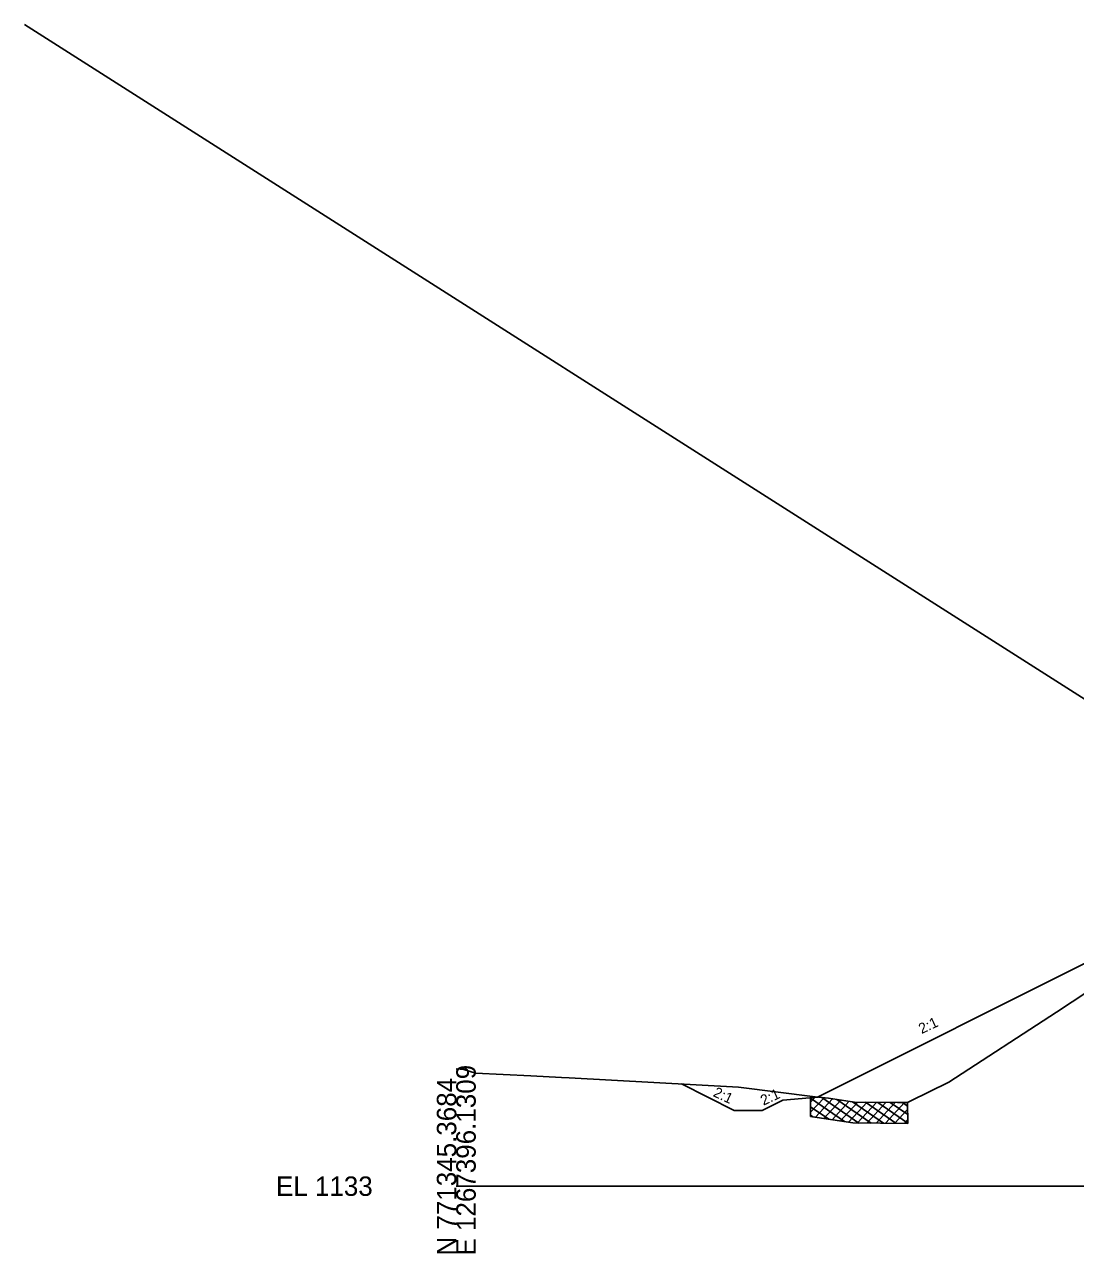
# Model space of a CAD drawing. Extents: x -3833 to 1267678, y -522 to 773248.
# Drawn here: x -62.2 to 89.3, y 7990.3 to 8167.4 of the extents above; entities that cross this region are included whole.
import ezdxf

# ---------------------------------------------------------------- set-up
doc = ezdxf.new("R2010")
doc.units = 0
for name, color, linetype in [('Exist Cross Section Cell', 7, 'Continuous'), ('Exist XS Ground Line', 7, 'Continuous'), ('Prop CMT DNC', 7, 'Continuous'), ('Prop XS Finish Grade', 7, 'Continuous'), ('Prop XS Label Text', 7, 'Continuous'), ('Prop XS Undercut Exc', 7, 'Continuous'), ('Scratch_Level_1', 7, 'Continuous')]:
    doc.layers.add(name, color=color, linetype=linetype)

msp = doc.modelspace()

# ---------------------------------------------------------------- linework, layer by layer
at = {"layer": 'Exist Cross Section Cell'}
msp.add_line((0, 8000), (150, 8000), dxfattribs=at)
at = {"layer": 'Exist XS Ground Line'}
for p, q in [((86.52, 8025.06), (97, 8032.03)), ((71.03, 8015.01), (86.52, 8025.06)), ((0, 8016.91), (1.11, 8016.8)), ((1.11, 8016.8), (2.77, 8016.27)), ((2.77, 8016.27), (10.76, 8015.89)), ((10.76, 8015.89), (15.17, 8015.66)), ((15.17, 8015.66), (16.26, 8015.63)), ((16.26, 8015.63), (40.7, 8014.27)), ((40.7, 8014.27), (51.73, 8012.87)), ((65.46, 8012.25), (71.03, 8015.01)), ((51.73, 8012.87), (53.67, 8012.7)), ((53.67, 8012.7), (57.44, 8012.11)), ((57.44, 8012.11), (63.61, 8012.06)), ((63.61, 8012.06), (65.05, 8012.04)), ((65.05, 8012.04), (65.46, 8012.25))]:
    msp.add_line(p, q, dxfattribs=at)
at = {"layer": 'Prop XS Finish Grade'}
msp.add_line((92.02, 8032.81), (52.08, 8012.84), dxfattribs=at)
msp.add_lwpolyline([(52.08, 8012.84), (47.08, 8012.42), (44.08, 8010.92), (40.08, 8010.92), (32.47, 8014.73)], dxfattribs=at)
at = {"layer": 'Prop XS Undercut Exc'}
for p, q in [((51.08, 8012.95), (51.08, 8010.06)), ((51.77, 8012.87), (51.08, 8012.12)), ((53.03, 8012.75), (51.08, 8010.65)), ((51.08, 8012.68), (55.99, 8009.3)), ((54.25, 8012.6), (51.79, 8009.95)), ((52.69, 8012.78), (58.03, 8009.1)), ((55.44, 8012.42), (52.99, 8009.77)), ((56.63, 8012.23), (54.18, 8009.58)), ((54.85, 8012.51), (59.82, 8009.09)), ((57.88, 8012.1), (55.37, 8009.39)), ((59.23, 8012.09), (56.56, 8009.21)), ((57.13, 8012.16), (61.6, 8009.08)), ((60.59, 8012.08), (57.83, 8009.11)), ((58.98, 8012.1), (63.39, 8009.06)), ((61.94, 8012.07), (59.18, 8009.09)), ((63.29, 8012.06), (60.53, 8009.08)), ((60.76, 8012.08), (65.13, 8009.08)), ((64.64, 8012.05), (61.89, 8009.07)), ((62.55, 8012.07), (65.09, 8010.31)), ((64.33, 8012.05), (65.06, 8011.55)), ((65.05, 8012.04), (65.13, 8009.05)), ((51.08, 8011.46), (53.71, 8009.65)), ((51.08, 8010.25), (51.43, 8010.01)), ((51.08, 8010.06), (57.2, 8009.11)), ((65.07, 8011.04), (63.24, 8009.07)), ((57.2, 8009.11), (65.13, 8009.05)), ((65.11, 8009.61), (64.59, 8009.05))]:
    msp.add_line(p, q, dxfattribs=at)
at = {"layer": 'Scratch_Level_1'}
msp.add_line((150, 8032.38), (-62.25, 8167.44), dxfattribs=at)

# ---------------------------------------------------------------- texts
at = {"layer": 'Exist Cross Section Cell'}
for s, p in [('E 1267396.1309', (2.8, 7990)), ('N 771345.3684', (0, 7990))]:
    msp.add_text(s, height=2.8, rotation=90, dxfattribs=at).set_placement(p)
msp.add_text('EL 1133', height=2.8, dxfattribs=at).set_placement((-26, 7998.6))
at = {"layer": 'Prop CMT DNC'}
msp.add_text('X', height=0.00025, dxfattribs=at).set_placement((50.57, 8013.02))
at = {"layer": 'Prop XS Label Text'}
for rotation, p in [(24.9367, (67.09, 8021.92)), (335.0633, (36.92, 8013.01)), (24.9367, (44.29, 8011.59))]:
    msp.add_text('2:1', height=1.5, rotation=rotation, dxfattribs=at).set_placement(p)

doc.saveas('drawing.dxf')
